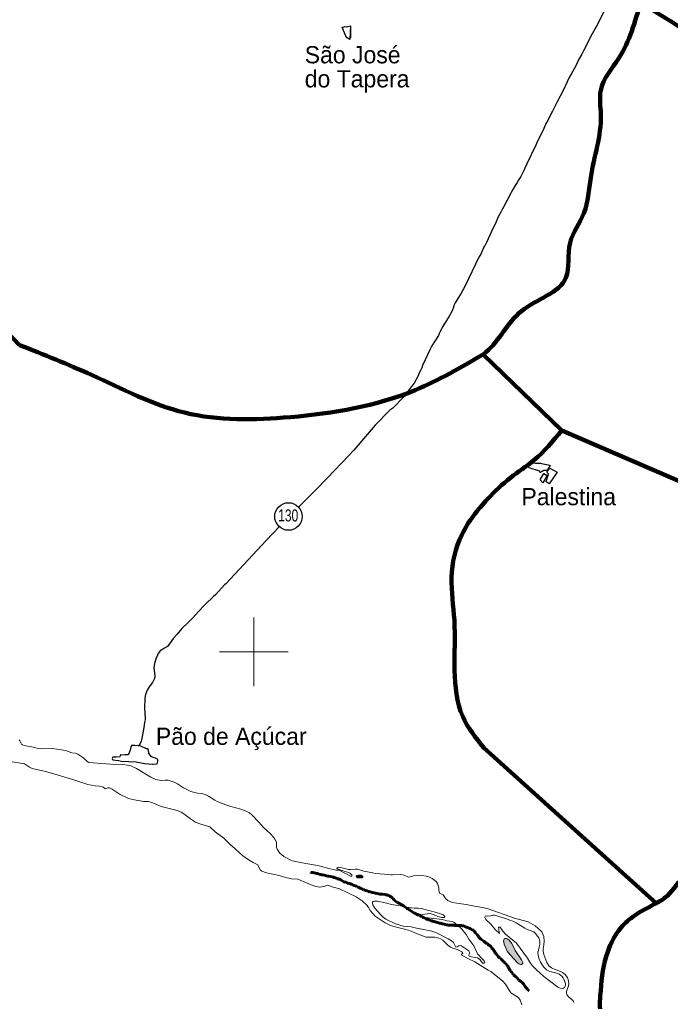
# Model space of a CAD drawing. Extents: x 553962 to 842807, y 8883888 to 9032388.
# Drawn here: x 668185 to 687117, y 8914830 to 8943398 of the extents above; entities that cross this region are included whole.
import ezdxf
from ezdxf.enums import TextEntityAlignment as Align

# ---------------------------------------------------------------- set-up
doc = ezdxf.new("R2010")
doc.units = 0
doc.header["$LTSCALE"] = 200
doc.linetypes.add('LONG_DASH_SHORT_DASH', pattern=[9.9, 6, -1.2, 1.5, -1.2])
for name, color, linetype, lineweight in [('12', 7, 'Continuous', 25), ('2', 7, 'Continuous', 13), ('21', 7, 'Continuous', 25), ('25', 7, 'Continuous', 13), ('48', 7, 'Continuous', 25), ('7', 7, 'LONG_DASH_SHORT_DASH', 60), ('9', 7, 'Continuous', 90)]:
    doc.layers.add(name, color=color, linetype=linetype, lineweight=lineweight)
doc.layers.add('41', color=7, linetype='Continuous')

msp = doc.modelspace()

# ---------------------------------------------------------------- hatches: boundary and pattern name
at = {"layer": '25'}
for points in [[(678121.8, 8918499.9), (678099.7, 8918499.9), (678072.1, 8918499.9), (678038.9, 8918499.9), (677994.7, 8918494.3), (677978.1, 8918477.8), (677983.7, 8918444.6), (678016.8, 8918422.5), (678066.5, 8918422.5), (678116.3, 8918422.5), (678155, 8918422.5), (678171.5, 8918439.1), (678171.5, 8918466.7), (678155, 8918483.3)], [(682604.9, 8916312), (682500, 8916511.3), (682424.9, 8916610.1), (682387.8, 8916643), (682346.5, 8916655.7), (682313.7, 8916655.9), (682284.1, 8916639.2), (682267.8, 8916618.9), (682264.6, 8916598.1), (682286.2, 8916495.1), (682370.8, 8916295.4), (682452, 8916180.6), (682682.3, 8915939.4), (682710.5, 8915920.7), (682762.8, 8915903.1), (682787.5, 8915903.3), (682820.9, 8915934.7), (682822.2, 8915960.7), (682782.3, 8916035.7)]]:
    msp.add_hatch(color=256, dxfattribs=at).paths.add_polyline_path(points)

# ---------------------------------------------------------------- linework, layer by layer
at = {"layer": '12'}
for points in [[(685809.3, 8944882.1), (685139.6, 8943558.4), (685005.6, 8943280), (684805.5, 8942915.9), (684644.9, 8942595.4), (684597.7, 8942511.3), (684542, 8942393.2), (684448.1, 8942230.3), (684406.6, 8942143.9)], [(684406.6, 8942143.9), (684365.6, 8942058.6), (684226.8, 8941813.7), (684226.8, 8941813.7), (684175, 8941710.1)], [(684175, 8941710.1), (684006.3, 8941354.9), (683811.8, 8940990.8), (683708.9, 8940774.6), (683683.4, 8940734.8), (683672.2, 8940709.1)], [(683672.2, 8940709.1), (683664.9, 8940692.3), (683518.7, 8940415.7), (683489.7, 8940375.6), (683483.7, 8940349.2)], [(683483.7, 8940349.2), (683483.6, 8940348.4), (683407.7, 8940165.2), (683245.4, 8939843.2), (683205.2, 8939743.2), (682941, 8939205.2)], [(682941, 8939205.2), (682878.1, 8939077.2), (682861.5, 8939025.1), (682765.5, 8938831.7), (682733.1, 8938786.5)], [(682733.1, 8938786.5), (682705.4, 8938747.7), (682658.5, 8938662.8), (682599.8, 8938576.1), (682535.5, 8938453.1), (682483.4, 8938370.4), (682473, 8938350.6)], [(682473, 8938350.6), (682268.3, 8937959.8), (682239.3, 8937915.4), (682190.6, 8937811.3), (682111.6, 8937663.4), (682046.3, 8937511.5), (681908.7, 8937232.2), (681767.3, 8936909.9), (681749, 8936876)], [(681749, 8936876), (681674.2, 8936737.5), (681598.8, 8936576.5), (681548, 8936488.8), (681147.4, 8935655.4), (681034.1, 8935439.7), (680978.2, 8935363.2), (680858.2, 8935160.4), (680821.2, 8935082.4), (680813.6, 8935058.9)], [(680813.6, 8935058.9), (680770.7, 8934925.3), (680678.2, 8934766.8), (680599.4, 8934646.3), (680530.2, 8934514.3), (680497.2, 8934464.9), (680407.8, 8934301.6), (680390.7, 8934262.8)], [(680390.7, 8934262.8), (680366.4, 8934207.8), (680262.3, 8934041.1), (680239.1, 8933996.7), (680210.5, 8933956.9), (680161.7, 8933865.8)], [(680161.7, 8933865.8), (680129.3, 8933805.3), (679909.7, 8933336.9), (679881.7, 8933269.9)], [(679881.7, 8933269.9), (679854, 8933203.9), (679812.6, 8933121.8), (679778.5, 8933035.9), (679658.3, 8932822.5), (679546.8, 8932670.6), (679434.3, 8932505.7), (679403.8, 8932469.2)], [(679403.8, 8932469.2), (679364.3, 8932422), (679243.8, 8932308), (679157.5, 8932211.5), (679038.6, 8932094.2), (678953.6, 8932030.6), (678525.5, 8931596.9), (677912.2, 8930867.7), (677764.4, 8930713.9), (677128.1, 8930052.4), (677127.3, 8930051.6)], [(677127.3, 8930051.6), (676803, 8929714.4), (676539.8, 8929451), (676316.9, 8929228)], [(675747.8, 8928644.7), (675357.8, 8928239.4), (674183.6, 8926978.8), (674145.1, 8926947.6), (673889.8, 8926674.1), (673817.5, 8926604.1)], [(673817.5, 8926604.1), (673601, 8926394.6), (673540.7, 8926341.3), (673385.9, 8926177.5), (673220, 8925987.8), (673060.2, 8925824.4), (672938.9, 8925717.3), (672905.6, 8925678)], [(672905.6, 8925678), (672769.2, 8925517), (672663.1, 8925399.6), (672486.7, 8925159.8), (672402.7, 8925104), (672277.3, 8925032.8), (672246.2, 8924995.7), (672220.2, 8924955.3), (672176.2, 8924860.7)], [(672176.2, 8924860.7), (672161.6, 8924829.2), (672110.6, 8924662), (672086.1, 8924531.1), (672095.5, 8924466.4)], [(672095.5, 8924466.4), (672118.8, 8924306.3), (672118.5, 8924278.5), (672104, 8924223.3), (672070.6, 8924145.4), (672047.1, 8924105), (671951.4, 8923978.3), (671897.8, 8923887.3), (671849.3, 8923755.3), (671827.1, 8923657.7), (671813, 8923357.8), (671840.2, 8923069), (671838.2, 8923027.3), (671822.3, 8922948), (671796.6, 8922795.7)], [(671796.6, 8922795.7), (671743.5, 8922481.6), (671721, 8922405.8), (671692.6, 8922335.7), (671657.6, 8922270.9)]]:
    msp.add_lwpolyline(points, dxfattribs=at)
at = {"layer": '2'}
for p, q in [((675000, 8924000), (675000, 8926000)), ((674000, 8925000), (676000, 8925000))]:
    msp.add_line(p, q, dxfattribs=at)
at = {"layer": '21'}
for points in [[(677564.5, 8943182.9), (677599.4, 8943181.8), (677648.6, 8943194.1), (677696.2, 8943191), (677743.9, 8943194.8), (677811.3, 8943218), (677815.7, 8943218.5), (677793.3, 8942820.7)], [(677793.3, 8942820.7), (677714, 8942864.2), (677676.2, 8942918.7), (677564.5, 8943182.9)], [(683365.8, 8930483.5), (683510.5, 8930449.7), (683558.2, 8930444.2), (683616.3, 8930424.2), (683575.5, 8930346.8), (683531.7, 8930288.7), (683504.4, 8930279.3), (683431.3, 8930282), (683384.2, 8930250.7), (683374.9, 8930248.7), (683369.1, 8930234.7), (683343.3, 8930224.6), (683323.7, 8930230), (683316.4, 8930247.3), (683294.6, 8930271.4), (683188.3, 8930293), (683121, 8930313.4), (683006.2, 8930359.9), (682988.3, 8930380), (682982.9, 8930417.6), (683011.5, 8930470.5), (683028.3, 8930482.1), (683057.5, 8930493), (683122.1, 8930496.8), (683191.3, 8930496.1)], [(683191.3, 8930496.1), (683299.3, 8930495), (683342.3, 8930487.2), (683365.8, 8930483.5)]]:
    msp.add_lwpolyline(points, dxfattribs=at)
at = {"layer": '21', "lineweight": 13}
for points in [[(677818.6, 8943060.4), (677817.1, 8942876.8), (677800.3, 8942857.8), (677789.7, 8942835.5), (677793.3, 8942820.7)], [(677811.4, 8943218.2), (677807.9, 8943209.5), (677818.9, 8943095.6), (677818.6, 8943060.4)]]:
    msp.add_lwpolyline(points, dxfattribs=at)
at = {"layer": '21'}
for points in [[(683437.4, 8930190.9), (683536.7, 8930129.6), (683409.5, 8929914.8), (683325.5, 8930009.4)], [(683526.5, 8930229.3), (683607.8, 8930349.4), (683826.7, 8930234.4), (683590.2, 8929894.4), (683503.7, 8929948.1), (683567.2, 8930185.8)], [(672070.8, 8921729.3), (672183.6, 8921744.1), (672204.3, 8921823.7), (672205.8, 8921869.8), (672137.9, 8921906.6), (672045.5, 8921936.8), (672015.8, 8921950.8), (671951.1, 8922034), (671936.7, 8922041.8), (671940.3, 8922071), (671928.8, 8922182.7), (671874.6, 8922176.6), (671712.4, 8922251.7), (671659.2, 8922270.3), (671636.6, 8922261.5), (671534.1, 8922275.4), (671438.6, 8922277.6), (671419.5, 8922227.5), (671398.3, 8922143), (671378.3, 8922092.9), (671356.9, 8922015.4), (671328.1, 8922006.3), (671250.4, 8922007.9), (671162.4, 8921997.4), (671116.6, 8922002), (671109.5, 8921989.5), (671105, 8921961.4), (671096.8, 8921948), (670990.1, 8921931.4), (670891.9, 8921937.6), (670878.8, 8921896.3), (670882.6, 8921866.1), (670900, 8921857.8), (670970.5, 8921845.4), (671059.8, 8921839.3), (671147.8, 8921823.2), (671572.8, 8921799.1), (671817.6, 8921756.7), (672050.9, 8921730.4)]]:
    msp.add_lwpolyline(points, close=True, dxfattribs=at)
at = {"layer": '25'}
for points in [[(668175.3, 8922440.9), (668193.4, 8922414.2), (668215.8, 8922353.1), (668240.8, 8922316.8), (668270.3, 8922290.6), (668317.3, 8922273.5), (668576.3, 8922231.4), (668724.7, 8922190.8), (668817.5, 8922180.4), (669130.5, 8922192.7), (669530, 8922132.2)], [(670613, 8921062.4), (670594.6, 8921075.1), (670505.7, 8921092.1), (670378.9, 8921097.7), (670172.5, 8921136.1), (669790.2, 8921268), (669181.6, 8921455.5), (668940.4, 8921522.2), (668553.3, 8921609.1), (668470.6, 8921646), (668322.8, 8921739.3), (667855.1, 8921816.8), (666980.9, 8921915.9), (665565.9, 8922078.1), (665402.5, 8922087.8), (665227.8, 8922071.5), (665027.5, 8922015.6), (664640.9, 8921845.5), (664531.1, 8921815.4)], [(669530, 8922132.2), (669551.5, 8922120.6), (669703.5, 8922065.4), (669805.2, 8922048.5), (669880.3, 8922022.2), (670051.3, 8921908.8), (670147.5, 8921810.8), (670198.9, 8921779.1), (670825.1, 8921729), (671173.4, 8921726.6), (671321.6, 8921707.8), (671424.1, 8921682), (671582.7, 8921606.9), (672004.6, 8921350.8), (672150.9, 8921284.8), (672299, 8921260.5), (672419, 8921266.9), (672503.5, 8921262.1), (672626.2, 8921231.8), (672681.9, 8921209.8), (672776.3, 8921157.4), (672954.4, 8921040.4), (673169, 8920938.3), (673363.4, 8920887.3), (673485, 8920874.1), (673583.2, 8920848.3), (673683.5, 8920804.3), (673860.5, 8920685.6), (673931.7, 8920649.3), (674185.8, 8920553)], [(674298.5, 8919404.1), (674291.8, 8919409.6), (674126, 8919575.4), (673873, 8919765.1), (673715.5, 8919905.3), (673623, 8919941.7), (673428.6, 8919993.5), (673296.8, 8920049), (673159.2, 8920137.6), (672965, 8920287.3), (672880.8, 8920337.6), (672764.4, 8920379.9), (672301.8, 8920503.9), (672059.4, 8920609.5), (671934.4, 8920643.4), (671799.8, 8920650.2), (671472.2, 8920703.7), (671336.9, 8920745), (671109.4, 8920850.7), (670878.6, 8921005.6), (670802.7, 8921042.5), (670751.6, 8921047.3), (670704.9, 8921020.2), (670678.6, 8921017.5), (670613, 8921062.4)], [(674185.8, 8920553), (674331.2, 8920497.9), (674621.4, 8920420.9), (674779.7, 8920369.3), (674871.4, 8920317.9), (674944.3, 8920262), (675153.1, 8920035), (675278.2, 8919884.7), (675471.8, 8919715.9), (675585, 8919594.2), (675613.6, 8919553.2), (675656.7, 8919458.2), (675661.4, 8919317.4), (675675.3, 8919257.8), (675757.5, 8919139.9), (675867.5, 8919047.4), (676076.8, 8918937.9), (676128.1, 8918918.2), (676257.4, 8918887.3), (676406.6, 8918860.2)], [(681818.1, 8915736.8), (681425.2, 8915979.8), (681222.6, 8916074.7), (681046.9, 8916174.6), (681037.6, 8916191.5), (681077.1, 8916231.5), (681069.9, 8916251.6), (681048.6, 8916272.8), (680945.8, 8916329.8), (680790.6, 8916373.3), (680721.3, 8916405.2), (680645.7, 8916462.9), (680494.3, 8916609.8), (680432, 8916649.9), (680383.3, 8916669.5), (680263.9, 8916694.5), (680070.5, 8916694.2), (680014.4, 8916702), (679728.1, 8916803.7), (679599.7, 8916864.4), (679494.1, 8916904.4), (679183.1, 8916978), (678970.2, 8917037.8), (678820.7, 8917111.4), (678532.7, 8917311.3), (678456, 8917383.8), (678383.1, 8917469.9), (678338.7, 8917561.6), (678294.1, 8917624), (678150.8, 8917757.7), (677973.1, 8917871.9), (677487.9, 8918104.1), (677281.9, 8918159.9), (677153.7, 8918215.1), (677037.8, 8918171.3), (676918, 8918157), (676801.9, 8918174.5), (676667.5, 8918220.7), (676277.6, 8918381.7), (676099, 8918399.2), (675895.4, 8918446.5), (675739.5, 8918492.1), (675362.3, 8918567.1), (675228.4, 8918616), (675184.7, 8918661.3), (675115.9, 8918805.8), (674978.6, 8918869.4), (674860.2, 8918934.9), (674677.5, 8919067.2), (674567.5, 8919159.4), (674447.6, 8919281.5), (674298.5, 8919404.1)], [(676406.6, 8918860.2), (676902.1, 8918770.1), (677144.9, 8918707)], [(677144.9, 8918707), (677387.7, 8918643.9), (677479.7, 8918643.7), (677807.2, 8918472.7), (677846.8, 8918474.7), (677858.5, 8918492.6), (677847.1, 8918512.3), (677791.3, 8918560.8), (677728, 8918593.3), (677591, 8918627.5), (677431.5, 8918690.2), (677417.9, 8918704.6), (677419.8, 8918723.9), (677467.7, 8918734.3), (677573, 8918719.1), (677754.5, 8918668.8), (677809.8, 8918666), (677950.6, 8918679.4), (678015.6, 8918673.9), (678201.6, 8918623.4), (678458.3, 8918568.7)], [(678458.3, 8918568.7), (678523.8, 8918554.7), (678798.8, 8918527.6), (678989.1, 8918516.6)], [(678989.1, 8918516.6), (679028.7, 8918514.3), (679274.2, 8918524.4), (679370.3, 8918504.3), (679498.9, 8918447.1), (679546, 8918450), (679679.3, 8918495.6), (679746.3, 8918505.8), (679902.1, 8918494.5), (680007.6, 8918474.6), (680113.5, 8918440.7), (680189.9, 8918405.5), (680305.8, 8918315.1), (680343.3, 8918257.1), (680379.9, 8918133), (680383.4, 8918063), (680402.5, 8917983.4), (680502.8, 8917929.2), (680579.7, 8917817.8), (680646.8, 8917765.9), (680703.4, 8917735.4), (680777.3, 8917710.3), (680908.5, 8917690.3)], [(680908.5, 8917690.3), (681178.8, 8917648.9), (681178.8, 8917648.9), (681466.4, 8917586.3), (681660.9, 8917561), (681819.1, 8917524), (682585, 8917249.1), (682980.6, 8917149.2), (683185, 8917028.5), (683336.3, 8916896.5), (683373.2, 8916850.2), (683438.1, 8916716.7), (683446.5, 8916578.6), (683436.2, 8916473.2), (683412.3, 8916362.4), (683413.5, 8916288.2), (683432.7, 8916191.5), (683521.7, 8915959.8), (683583.7, 8915866.4), (683658.1, 8915805.7), (683712.5, 8915774.1), (683868, 8915721.3), (683982.8, 8915668.3), (684052.7, 8915615.1), (684096.7, 8915566.3), (684127.5, 8915511.8), (684143.1, 8915466.3), (684159.4, 8915351.3), (684151.8, 8915280.7), (684110.2, 8915174.9), (684097.4, 8915119.6), (684096.5, 8915064.6), (684118.2, 8915014.1), (684161.6, 8914954.8), (684253, 8914886), (684293.4, 8914843.8), (684308.7, 8914798.6)], [(682000.3, 8915611.7), (681893.5, 8915696.4), (681818.1, 8915736.8)], [(682796, 8914726.4), (682745.7, 8914861.4), (682705.5, 8914922.4), (682654, 8914970.7), (682479.2, 8915081.6), (682322.4, 8915329.9), (682232.1, 8915427.7), (682000.3, 8915611.7)]]:
    msp.add_lwpolyline(points, dxfattribs=at)
for points in [[(678121.8, 8918499.9), (678099.7, 8918499.9), (678072.1, 8918499.9), (678038.9, 8918499.9), (677994.7, 8918494.3), (677978.1, 8918477.8), (677983.7, 8918444.6), (678016.8, 8918422.5), (678066.5, 8918422.5), (678116.3, 8918422.5), (678155, 8918422.5), (678171.5, 8918439.1), (678171.5, 8918466.7), (678155, 8918483.3)], [(681051.6, 8916931.9), (680917.2, 8917059.9), (680829.5, 8917121.2), (680764.3, 8917152.8), (680618.1, 8917176), (680486.7, 8917212.2), (679908, 8917275.5), (679762, 8917317), (679635.4, 8917396.8), (679910.2, 8917356.6), (680118, 8917385), (680224.5, 8917353.5), (680354.4, 8917300.2), (680468.1, 8917272.3), (680544.4, 8917273.7), (680558.6, 8917291.6), (680515, 8917345.8), (680314, 8917417.1), (679871.3, 8917537.1), (679776.1, 8917543.1), (679665.5, 8917539.2), (679433.9, 8917573.7), (679267.9, 8917609.1), (678996.5, 8917647.8), (678870.4, 8917690.1), (678589.1, 8917741.1), (678498, 8917744.3), (678469.7, 8917732.7), (678455.1, 8917717), (678451.8, 8917673.4), (678458.9, 8917639.2), (678523.3, 8917543), (678679.2, 8917360), (678761.9, 8917279.4), (678835.3, 8917221.6), (679118.2, 8917086.7), (679346.3, 8917013.9), (679576.6, 8917001.6), (679730.2, 8916958.4), (679899.8, 8916930.5), (680176.7, 8916871.1), (680311.5, 8916821.6), (680651, 8916653.5), (680752.3, 8916589.8), (680805.3, 8916538.2), (680876.6, 8916411.5), (680909.3, 8916413.3), (680957.8, 8916448.8), (681016.5, 8916451.2), (681252.3, 8916299.6), (681267.3, 8916278.3), (681272.5, 8916243.6), (681254.2, 8916164.9), (681262.6, 8916146.7), (681320.4, 8916124.1), (681503.1, 8916094), (681572.9, 8916043.7), (681643.2, 8915956.4), (681671.9, 8915935.7), (681689.5, 8915938.5), (681714.4, 8915957.7), (681702.9, 8916012.5), (681637.7, 8916065.1), (681506.7, 8916216.1), (681398.2, 8916446.9), (681252.7, 8916642.9), (681172.9, 8916771.4)], [(683098.8, 8915878.5), (683218, 8915745.7), (683431.3, 8915549.3), (683842.3, 8915241.8), (683914.8, 8915211.4), (683988.1, 8915206.1), (684032.5, 8915231.8), (684070.1, 8915304), (684063.1, 8915352.3), (684022, 8915472.5), (683998.8, 8915515.4), (683957.9, 8915563.1), (683881.6, 8915617.7), (683813.4, 8915653.2), (683609.3, 8915703.3), (683514, 8915743.9), (683424.3, 8915831.4), (683340.7, 8915966.9), (683294.1, 8916091.3), (683261.6, 8916230.6), (683318.9, 8916497.7), (683318.9, 8916580.9), (683285.7, 8916678.7), (683188.7, 8916805.8), (683140.2, 8916850.4), (683094.9, 8916876.6), (682950.1, 8916924.1), (682886.8, 8916955.4), (682635, 8917119.5), (682537.5, 8917164.5), (682468.1, 8917183.6), (682346, 8917233.6), (681999.5, 8917342.7), (681956.9, 8917341.8), (681867.4, 8917308.4), (681794.8, 8917322), (681728.3, 8917312.8), (681716.4, 8917267.4), (681747.4, 8917215.7), (681890.3, 8917076.4), (682019, 8916922.4), (682142.9, 8916807.4), (682119.7, 8916983.6), (682130.7, 8916993.2), (682166.1, 8916989.6), (682243.8, 8916875.1), (682318.3, 8916790), (682638.3, 8916523.7), (682962.6, 8916089.6), (683031.4, 8915973.4)], [(682604.9, 8916312), (682500, 8916511.3), (682424.9, 8916610.1), (682387.8, 8916643), (682346.5, 8916655.7), (682313.7, 8916655.9), (682284.1, 8916639.2), (682267.8, 8916618.9), (682264.6, 8916598.1), (682286.2, 8916495.1), (682370.8, 8916295.4), (682452, 8916180.6), (682682.3, 8915939.4), (682710.5, 8915920.7), (682762.8, 8915903.1), (682787.5, 8915903.3), (682820.9, 8915934.7), (682822.2, 8915960.7), (682782.3, 8916035.7)]]:
    msp.add_lwpolyline(points, close=True, dxfattribs=at)
at = {"layer": '48'}
msp.add_circle((676006.2, 8928939.6), 401.3, dxfattribs=at)
at = {"layer": '7'}
for points in [[(677045, 8918504), (677001.7, 8918514.2), (676981.3, 8918516.8), (676940.6, 8918524.4), (676910.1, 8918524.4), (676869.4, 8918547.4), (676828.7, 8918555.1), (676714.1, 8918578.1), (676660.7, 8918583.2), (676646.3, 8918587.3)], [(679307.3, 8917640.1), (679279.3, 8917660.5), (679246.2, 8917678.4), (679213.1, 8917688.6), (679182.6, 8917709.1), (679152.1, 8917727), (679121.5, 8917747.4), (679075.7, 8917785.8), (679050.2, 8917819), (679024.8, 8917839.4), (678994.2, 8917872.7), (678958.6, 8917890.6), (678925.5, 8917908.4), (678892.5, 8917916.1), (678869.6, 8917923.8), (678826.3, 8917939.1), (678742.3, 8917946.8), (678666, 8917951.9), (678584.6, 8917972.3), (678538.8, 8917974.9), (678498, 8917992.8), (678452.2, 8918000.5), (678383.5, 8918020.9), (678347.9, 8918031.1), (678325, 8918031.1), (678279.2, 8918054.1), (678243.6, 8918059.2), (678202.8, 8918077.1), (678182.5, 8918092.5), (678149.4, 8918097.6), (678121.4, 8918118), (678093.4, 8918123.2), (678057.8, 8918143.6), (678029.8, 8918158.9), (677999.2, 8918158.9), (677981.4, 8918179.4), (677950.9, 8918189.6), (677920.4, 8918204.9), (677892.4, 8918212.6), (677856.7, 8918235.6), (677828.7, 8918243.3), (677790.6, 8918256.1), (677757.5, 8918263.7), (677737.1, 8918271.4), (677683.7, 8918294.4), (677653.2, 8918302.1), (677620.1, 8918309.7), (677592.1, 8918330.2), (677559, 8918345.5), (677525.9, 8918366), (677492.8, 8918381.3), (677467.4, 8918391.5), (677447, 8918396.7), (677419, 8918399.2), (677393.6, 8918417.1), (677365.6, 8918424.8), (677332.5, 8918435), (677312.1, 8918442.7), (677279.1, 8918450.3), (677225.6, 8918460.6), (677172.2, 8918470.8), (677151.8, 8918475.9), (677116.2, 8918486.1), (677080.6, 8918493.8), (677045, 8918504)], [(680338, 8917126.3), (680304.9, 8917136.5), (680271.8, 8917144.2), (680248.9, 8917149.3), (680218.4, 8917157), (680172.6, 8917174.9), (680142.1, 8917185.1), (680106.4, 8917197.9), (680086.1, 8917205.5), (680065.7, 8917208.1), (680032.6, 8917226), (680012.3, 8917236.2), (679986.8, 8917246.4), (679966.5, 8917254.1), (679935.9, 8917266.9), (679910.5, 8917277.1), (679882.5, 8917300.1), (679851.9, 8917310.3), (679816.3, 8917333.3), (679783.2, 8917353.8), (679757.8, 8917358.9), (679729.8, 8917364), (679704.3, 8917387), (679684, 8917397.2), (679663.6, 8917397.2), (679622.9, 8917425.3), (679594.9, 8917443.2), (679569.5, 8917461.1), (679541.5, 8917481.6), (679505.8, 8917509.7), (679475.3, 8917517.4), (679447.3, 8917537.8), (679421.8, 8917558.3), (679391.3, 8917578.7), (679363.3, 8917599.2), (679332.8, 8917632.4), (679307.3, 8917640.1)], [(682076.2, 8916175.4), (682050.8, 8916211.2), (682020.2, 8916241.9), (681987.1, 8916298.1), (681969.3, 8916331.4), (681936.2, 8916367.1), (681926, 8916387.6), (681895.5, 8916423.4), (681870, 8916443.8), (681836.9, 8916464.3), (681816.6, 8916482.2), (681793.7, 8916502.6), (681765.7, 8916520.5), (681730, 8916543.5), (681689.3, 8916581.9), (681663.9, 8916599.8), (681633.3, 8916620.2), (681605.3, 8916638.1), (681587.5, 8916658.5), (681564.6, 8916676.4), (681549.3, 8916696.9), (681521.3, 8916732.7), (681501, 8916753.1), (681483.1, 8916781.2), (681455.1, 8916801.7), (681434.8, 8916837.5), (681417, 8916870.7), (681368.6, 8916906.5), (681348.2, 8916921.8), (681320.2, 8916924.4), (681305, 8916944.8), (681266.8, 8916962.7), (681218.4, 8916978.1), (681190.5, 8916980.6), (681170.1, 8917001.1), (681139.6, 8917008.7), (681106.5, 8917024.1), (681073.4, 8917026.6), (681040.3, 8917036.8), (681014.9, 8917036.8), (680994.5, 8917036.8), (680958.9, 8917036.8), (680913.1, 8917041.9), (680877.5, 8917041.9), (680846.9, 8917041.9), (680816.4, 8917044.5), (680796, 8917044.5), (680765.5, 8917044.5), (680735, 8917044.5), (680714.6, 8917047.1), (680694.3, 8917047.1), (680673.9, 8917047.1), (680653.5, 8917052.2), (680623, 8917054.7), (680602.7, 8917057.3), (680564.5, 8917064.9), (680536.5, 8917072.6), (680516.1, 8917075.2), (680495.8, 8917082.8), (680475.4, 8917087.9), (680447.4, 8917093.1), (680427.1, 8917103.3), (680399.1, 8917108.4), (680368.5, 8917118.6), (680338, 8917126.3)], [(683007.9, 8915140.2), (682972.3, 8915163.2), (682951.9, 8915193.9), (682934.1, 8915214.3), (682916.2, 8915247.6), (682890.8, 8915262.9), (682873, 8915296.1), (682842.4, 8915342.1), (682811.9, 8915372.8), (682773.7, 8915395.8), (682750.8, 8915426.5), (682712.6, 8915444.4), (682689.7, 8915475.1), (682656.6, 8915513.4), (682626.1, 8915533.8), (682593, 8915572.2), (682557.3, 8915595.2), (682537, 8915636.1), (682501.3, 8915664.2), (682483.5, 8915707.7), (682450.4, 8915733.2), (682399.5, 8915838), (682371.5, 8915863.6), (682356.2, 8915899.4), (682328.2, 8915919.8), (682305.3, 8915958.2), (682262.1, 8915978.6), (682236.6, 8916016.9), (682201, 8916052.7), (682170.4, 8916086), (682142.4, 8916098.8), (682124.6, 8916119.2), (682106.8, 8916139.7), (682076.2, 8916175.4)]]:
    msp.add_lwpolyline(points, dxfattribs=at)
at = {"layer": '9'}
msp.add_line((686702.4, 8917687.5), (681689.3, 8922210.8), dxfattribs=at)
for points in [[(645793.1, 8949290.9), (653495.4, 8947850), (659002.1, 8941889), (662654, 8939737.7), (668185.2, 8933928.8)], [(688969.4, 8929279), (683955, 8931444.8), (681670, 8933656.4)]]:
    msp.add_lwpolyline(points, dxfattribs=at)
for points in [[(637260.6, 8972975.8), (641524.5, 8971056.2), (652526.1, 8965412.7), (653164.3, 8965062.8), (670790.5, 8953770.1), (686194, 8943929.9), (696283.3, 8937647.1)], [(681670, 8933656.4), (681750.3, 8933721.2), (682786.5, 8934918.4), (684078.6, 8935889.6), (684199.9, 8936903.1), (684601.9, 8937766.8), (684799.3, 8938806.1), (685093.9, 8940631), (685089.7, 8941339.8), (685618.5, 8942280.3), (686244, 8943891.1)], [(668185.2, 8933928.8), (670277.1, 8933057.6), (672981.1, 8931962.8), (676061.1, 8931832.8), (679695.5, 8932618), (681670, 8933656.4)], [(681689.3, 8922210.8), (681075.2, 8923117.8), (680840, 8924458.2), (680832.7, 8925926.8), (680750.4, 8927167), (681049, 8928410), (681805.8, 8929453.8), (682463.2, 8930066.4), (683146.5, 8930577.9), (683955, 8931444.8)], [(685563.3, 8914000.1), (685411.9, 8914186), (685156.8, 8914412), (685077.7, 8914993.8), (685249.9, 8916134.6), (685677.5, 8916973.4), (686082.1, 8917330.9), (686664.7, 8917664.4), (687019.1, 8917894.9), (687575, 8918481.4), (688360.8, 8918816.4), (688404.9, 8918868.1)]]:
    msp.add_spline(points, degree=3, dxfattribs=at)

# ---------------------------------------------------------------- texts
at = {"layer": '41'}
for s, p in [('São José', (676479.4, 8942126.7)), ('do Tapera', (676479.4, 8941426.7)), ('Pão de Açúcar', (672147.8, 8922293.7))]:
    msp.add_text(s, height=500, dxfattribs=at).set_placement(p)
msp.add_text('Palestina', height=500, dxfattribs=at).set_placement((684159.7, 8929266.8), align=Align.CENTER)
at = {"layer": '48', "width": 0.75}
msp.add_text('130', height=350, dxfattribs=at).set_placement((675998.5, 8928796.1), align=Align.CENTER)

doc.saveas('drawing.dxf')
